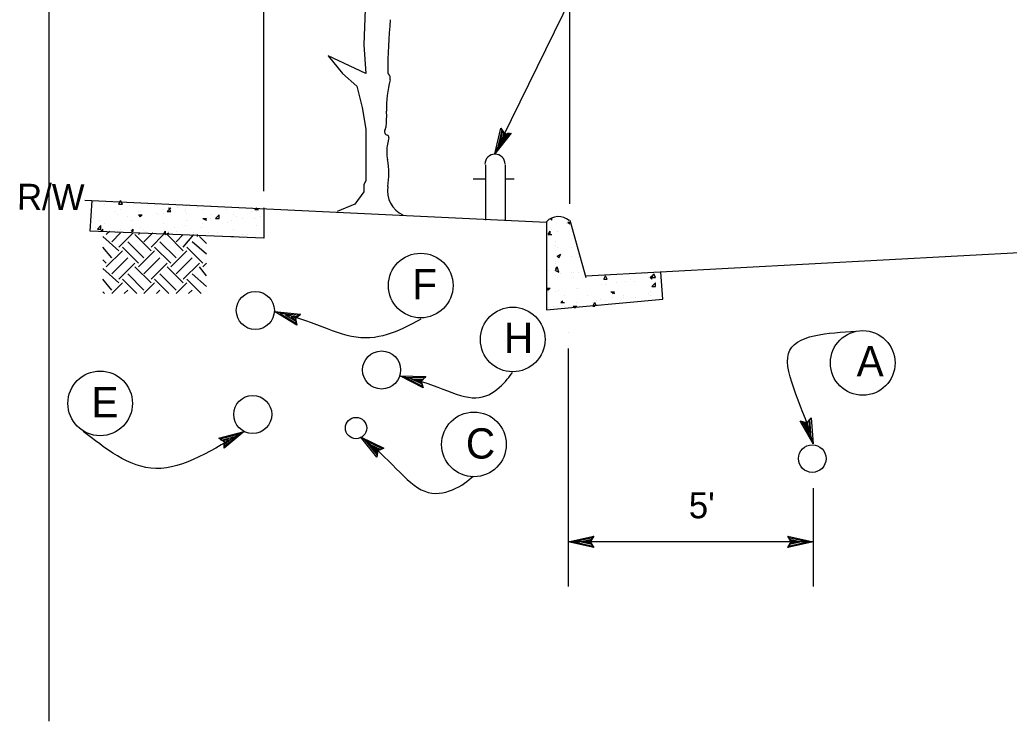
# Model space of a CAD drawing. Extents: x -119017 to -116080, y -104449 to -102845.
# Drawn here: x -118751.6 to -118523, y -103240.9 to -103078.8 of the extents above; entities that cross this region are included whole.
import ezdxf

# ---------------------------------------------------------------- set-up
doc = ezdxf.new("R2010")
doc.units = 0
for name, color, linetype in [('G-MARK', 7, 'Continuous'), ('G-TEXT', 7, 'Continuous'), ('Misc CnstDet(22)', 7, 'Continuous')]:
    doc.layers.add(name, color=color, linetype=linetype)

msp = doc.modelspace()

# ---------------------------------------------------------------- linework, layer by layer
at = {"layer": 'G-MARK'}
for p, q in [((-118695.17, -103118.46), (-118695.17, -103063.48)), ((-118624.48, -103121.36), (-118624.48, -103063.48)), ((-118624.9, -103154.84), (-118624.9, -103209.82)), ((-118568.26, -103187.09), (-118568.26, -103209.82)), ((-118568.26, -103199.49), (-118624.9, -103199.49))]:
    msp.add_line(p, q, dxfattribs=at)
msp.add_lwpolyline([(-118641.89, -103109.89), (-118614.2, -103053.25), (-118603.86, -103053.25)], dxfattribs=at)
for centre in [(-118658.96, -103140.25), (-118637.7, -103152.72), (-118556.82, -103158.14), (-118733.02, -103167.48), (-118646.66, -103176.97)]:
    msp.add_circle(centre, 7.47, dxfattribs=at)
for points in [[(-118692.74, -103146.26), (-118684.47, -103147.92), (-118672.48, -103155.77), (-118661.74, -103149.57), (-118658.84, -103147.92)], [(-118568.31, -103176.85), (-118569.96, -103169.41), (-118580.71, -103151.64), (-118564.59, -103151.23), (-118558.39, -103150.81)], [(-118663.8, -103161.15), (-118656.36, -103162.39), (-118644.79, -103170.24), (-118639, -103161.97), (-118637.76, -103160.32)], [(-118699.77, -103173.96), (-118706.79, -103178.1), (-118720.85, -103187.19), (-118732.01, -103177.68), (-118736.97, -103173.96)], [(-118672.9, -103175.2), (-118666.28, -103179.75), (-118658.43, -103192.56), (-118648.92, -103186.36), (-118646.85, -103184.3)]]:
    msp.add_open_spline(points, degree=3, dxfattribs=at)
at = {"layer": 'G-TEXT'}
for points in [[(-118638.06, -103105.07), (-118641.85, -103109.79), (-118640.42, -103103.91), (-118640.2, -103104.26), (-118641.25, -103108.56), (-118638.47, -103105.11), (-118638.87, -103105.14), (-118640.65, -103107.35), (-118639.98, -103104.6), (-118639.76, -103104.94), (-118640.05, -103106.13), (-118639.28, -103105.17), (-118639.59, -103105.2), (-118640.42, -103103.91), (-118639.59, -103105.2)], [(-118687.56, -103149.39), (-118692.74, -103146.26), (-118686.72, -103146.9), (-118687.03, -103147.16), (-118691.44, -103146.7), (-118687.64, -103148.99), (-118687.73, -103148.59), (-118690.16, -103147.13), (-118687.34, -103147.42), (-118687.65, -103147.69), (-118688.87, -103147.56), (-118687.82, -103148.2), (-118687.89, -103147.89), (-118686.72, -103146.9), (-118687.89, -103147.89)], [(-118658.4, -103163.86), (-118663.8, -103161.15), (-118657.76, -103161.31), (-118658.04, -103161.6), (-118662.47, -103161.48), (-118658.51, -103163.47), (-118658.63, -103163.08), (-118661.17, -103161.81), (-118658.33, -103161.89), (-118658.62, -103162.18), (-118659.85, -103162.14), (-118658.75, -103162.7), (-118658.84, -103162.39), (-118657.76, -103161.31), (-118658.84, -103162.39)], [(-118568.76, -103170.82), (-118568.31, -103176.85), (-118571.28, -103171.58), (-118570.88, -103171.68), (-118568.71, -103175.55), (-118569.03, -103171.12), (-118569.31, -103171.42), (-118569.1, -103174.25), (-118570.49, -103171.78), (-118570.09, -103171.88), (-118569.49, -103172.95), (-118569.58, -103171.72), (-118569.79, -103171.96), (-118571.28, -103171.58), (-118569.79, -103171.96)], [(-118705.61, -103175.53), (-118699.77, -103173.96), (-118704.39, -103177.86), (-118704.37, -103177.46), (-118700.98, -103174.6), (-118705.26, -103175.75), (-118704.92, -103175.96), (-118702.18, -103175.22), (-118704.34, -103177.05), (-118704.32, -103176.64), (-118703.38, -103175.85), (-118704.57, -103176.17), (-118704.3, -103176.34), (-118704.39, -103177.86), (-118704.3, -103176.34)], [(-118669.06, -103179.88), (-118672.9, -103175.2), (-118667.44, -103177.82), (-118667.82, -103177.96), (-118671.82, -103176.04), (-118669.01, -103179.48), (-118668.96, -103179.08), (-118670.76, -103176.88), (-118668.2, -103178.11), (-118668.58, -103178.25), (-118669.69, -103177.72), (-118668.91, -103178.67), (-118668.87, -103178.36), (-118667.44, -103177.82), (-118668.87, -103178.36)], [(-118618.99, -103200.81), (-118624.9, -103199.49), (-118618.99, -103198.18), (-118619.2, -103198.53), (-118623.53, -103199.48), (-118619.2, -103200.46), (-118619.41, -103200.11), (-118622.18, -103199.49), (-118619.41, -103198.88), (-118619.62, -103199.23), (-118620.82, -103199.49), (-118619.62, -103199.76), (-118619.78, -103199.49), (-118618.99, -103198.18), (-118619.78, -103199.49)], [(-118574.17, -103198.17), (-118568.26, -103199.49), (-118574.17, -103200.8), (-118573.96, -103200.45), (-118569.63, -103199.49), (-118573.96, -103198.52), (-118573.75, -103198.87), (-118570.98, -103199.49), (-118573.75, -103200.1), (-118573.54, -103199.75), (-118572.34, -103199.49), (-118573.54, -103199.22), (-118573.38, -103199.49), (-118574.17, -103200.8), (-118573.38, -103199.49)]]:
    msp.add_lwpolyline(points, close=True, dxfattribs=at)
at = {"layer": 'Misc CnstDet(22)'}
for p, q in [((-118744.83, -103240.93), (-118744.83, -102917.66)), ((-118624.48, -103121.36), (-118624.48, -103063.48)), ((-118643.96, -103112.37), (-118643.96, -103125.18)), ((-118639.41, -103112.37), (-118639.41, -103125.18)), ((-118643.96, -103115.67), (-118646.85, -103115.67)), ((-118637.35, -103115.67), (-118639.41, -103115.67)), ((-118736.6, -103120.5), (-118629.9, -103125.6)), ((-118735.32, -103127.66), (-118734.9, -103120.63)), ((-118734.49, -103121.05), (-118734.49, -103121.05)), ((-118734.49, -103121.46), (-118734.49, -103121.46)), ((-118732.01, -103121.46), (-118732.01, -103121.46)), ((-118730.36, -103121.05), (-118730.36, -103121.05)), ((-118728.7, -103121.46), (-118728.29, -103120.63)), ((-118728.7, -103121.46), (-118727.88, -103121.46)), ((-118727.88, -103121.46), (-118728.29, -103120.63)), ((-118726.22, -103121.87), (-118726.22, -103121.87)), ((-118722.09, -103121.87), (-118722.09, -103121.87)), ((-118720.44, -103121.87), (-118720.44, -103121.87)), ((-118713, -103121.87), (-118713, -103121.87)), ((-118707.21, -103121.87), (-118707.21, -103121.87)), ((-118734.49, -103123.94), (-118734.49, -103123.94)), ((-118729.53, -103123.11), (-118729.53, -103123.11)), ((-118729.12, -103123.94), (-118729.12, -103123.94)), ((-118728.29, -103122.7), (-118728.29, -103122.7)), ((-118724.16, -103123.11), (-118724.16, -103123.11)), ((-118724.16, -103123.94), (-118723.74, -103124.36)), ((-118724.16, -103123.94), (-118723.33, -103123.94)), ((-118723.74, -103123.11), (-118723.74, -103123.11)), ((-118723.74, -103123.94), (-118723.74, -103123.94)), ((-118723.74, -103124.36), (-118723.33, -103123.94)), ((-118720.02, -103123.53), (-118720.02, -103123.53)), ((-118719.61, -103123.94), (-118719.61, -103123.94)), ((-118718.37, -103122.7), (-118718.37, -103122.7)), ((-118718.37, -103123.53), (-118718.37, -103123.53)), ((-118717.54, -103123.11), (-118716.72, -103122.29)), ((-118717.54, -103123.11), (-118716.72, -103123.11)), ((-118716.72, -103123.11), (-118717.13, -103122.29)), ((-118715.06, -103122.29), (-118715.06, -103122.29)), ((-118713.41, -103122.7), (-118713.41, -103122.7)), ((-118713.41, -103123.11), (-118713.41, -103123.11)), ((-118713, -103123.53), (-118713, -103123.53)), ((-118710.52, -103122.29), (-118710.52, -103122.29)), ((-118709.27, -103122.7), (-118709.27, -103122.7)), ((-118707.21, -103123.94), (-118707.21, -103123.94)), ((-118706.38, -103124.77), (-118705.55, -103123.94)), ((-118705.55, -103124.77), (-118705.55, -103123.94)), ((-118703.9, -103122.7), (-118703.9, -103122.7)), ((-118702.25, -103123.94), (-118702.25, -103123.94)), ((-118698.11, -103123.11), (-118698.11, -103123.11)), ((-118697.29, -103122.7), (-118696.87, -103122.29)), ((-118697.29, -103122.7), (-118696.46, -103122.7)), ((-118696.87, -103122.7), (-118696.87, -103122.29)), ((-118696.87, -103123.11), (-118696.87, -103123.11)), ((-118695.22, -103122.29), (-118695.22, -103129.32)), ((-118695.17, -103122.19), (-118695.17, -103122.19)), ((-118734.49, -103124.77), (-118734.49, -103124.77)), ((-118733.66, -103127.25), (-118732.84, -103126.42)), ((-118733.25, -103125.18), (-118733.25, -103125.18)), ((-118732.84, -103127.25), (-118732.84, -103126.42)), ((-118732.01, -103126.01), (-118732.01, -103126.01)), ((-118726.64, -103124.36), (-118726.64, -103124.36)), ((-118725.81, -103125.18), (-118725.81, -103125.18)), ((-118718.37, -103126.01), (-118718.37, -103126.01)), ((-118713.41, -103126.42), (-118713.41, -103126.42)), ((-118713, -103125.18), (-118713, -103125.18)), ((-118709.27, -103124.77), (-118708.45, -103125.18)), ((-118709.27, -103124.77), (-118708.45, -103124.77)), ((-118709.27, -103126.01), (-118709.27, -103126.01)), ((-118708.86, -103125.18), (-118708.45, -103124.77)), ((-118707.62, -103124.77), (-118707.62, -103124.77)), ((-118706.38, -103124.77), (-118705.55, -103124.77)), ((-118703.49, -103125.6), (-118703.49, -103125.6)), ((-118702.66, -103125.18), (-118702.66, -103125.18)), ((-118701.42, -103124.36), (-118701.42, -103124.36)), ((-118700.18, -103124.77), (-118700.18, -103124.77)), ((-118697.29, -103124.77), (-118697.29, -103124.77)), ((-118696.87, -103126.42), (-118696.87, -103126.42)), ((-118696.05, -103124.36), (-118696.05, -103124.36)), ((-118696.05, -103124.36), (-118696.05, -103124.36)), ((-118629.9, -103125.6), (-118629.9, -103145.85)), ((-118629.9, -103126.42), (-118629.9, -103126.42)), ((-118629.08, -103124.77), (-118628.66, -103125.18)), ((-118628.66, -103125.18), (-118628.66, -103124.77)), ((-118625.36, -103126.01), (-118625.36, -103126.01)), ((-118624.94, -103125.6), (-118624.53, -103126.01)), ((-118624.94, -103125.6), (-118624.53, -103125.6)), ((-118624.94, -103126.01), (-118624.94, -103126.01)), ((-118624.53, -103125.18), (-118620.81, -103138.41)), ((-118624.53, -103126.01), (-118624.53, -103126.01)), ((-118624.48, -103125.08), (-118624.48, -103125.08)), ((-118624.48, -103125.08), (-118624.48, -103125.08)), ((-118695.22, -103129.32), (-118735.32, -103127.66)), ((-118734.08, -103126.84), (-118734.08, -103126.84)), ((-118733.66, -103127.25), (-118732.84, -103127.25)), ((-118732.84, -103127.66), (-118732.42, -103127.25)), ((-118732.84, -103127.66), (-118732.42, -103127.66)), ((-118732.42, -103127.66), (-118732.42, -103127.25)), ((-118731.6, -103128.49), (-118730.77, -103127.66)), ((-118730.36, -103130.14), (-118728.29, -103128.08)), ((-118729.12, -103127.66), (-118729.12, -103127.66)), ((-118728.7, -103131.38), (-118725.4, -103128.08)), ((-118728.29, -103127.25), (-118728.29, -103127.25)), ((-118725.81, -103127.66), (-118725.4, -103127.25)), ((-118725.81, -103127.66), (-118725.4, -103127.66)), ((-118725.4, -103127.66), (-118725.4, -103127.25)), ((-118721.26, -103132.21), (-118724.98, -103128.49)), ((-118724.16, -103128.49), (-118723.74, -103128.08)), ((-118723.74, -103126.84), (-118723.74, -103126.84)), ((-118722.92, -103127.25), (-118722.92, -103127.25)), ((-118722.92, -103130.14), (-118720.85, -103128.08)), ((-118722.5, -103127.66), (-118722.5, -103127.66)), ((-118721.26, -103131.38), (-118718.37, -103128.49)), ((-118718.37, -103128.49), (-118717.96, -103127.66)), ((-118717.96, -103128.49), (-118717.96, -103127.66)), ((-118717.96, -103128.49), (-118717.13, -103128.08)), ((-118717.96, -103128.49), (-118717.96, -103128.49)), ((-118717.54, -103128.49), (-118717.13, -103128.08)), ((-118713.82, -103132.21), (-118717.54, -103128.49)), ((-118717.13, -103127.66), (-118717.13, -103127.66)), ((-118716.72, -103128.49), (-118716.72, -103128.49)), ((-118715.89, -103126.84), (-118715.89, -103126.84)), ((-118715.48, -103127.66), (-118715.48, -103127.66)), ((-118715.48, -103130.14), (-118713.82, -103128.49)), ((-118713.82, -103131.38), (-118711.34, -103128.49)), ((-118711.34, -103128.08), (-118711.34, -103128.08)), ((-118710.52, -103128.9), (-118710.52, -103128.49)), ((-118710.52, -103128.9), (-118710.52, -103128.49)), ((-118709.69, -103126.84), (-118709.69, -103126.84)), ((-118708.03, -103128.08), (-118708.03, -103128.08)), ((-118705.97, -103128.08), (-118705.97, -103128.08)), ((-118702.25, -103127.25), (-118702.25, -103127.25)), ((-118700.18, -103128.49), (-118700.18, -103128.49)), ((-118698.94, -103128.49), (-118698.94, -103128.49)), ((-118629.49, -103128.49), (-118629.08, -103127.66)), ((-118629.49, -103128.49), (-118628.66, -103128.49)), ((-118629.08, -103126.84), (-118629.08, -103126.84)), ((-118629.08, -103128.49), (-118629.08, -103127.66)), ((-118628.66, -103127.25), (-118628.66, -103127.25)), ((-118627.42, -103127.66), (-118627.42, -103127.66)), ((-118620.81, -103138), (-118436.44, -103128.08)), ((-118728.7, -103132.21), (-118732.42, -103128.9)), ((-118722.92, -103133.86), (-118726.64, -103130.14)), ((-118715.48, -103133.86), (-118719.2, -103130.14)), ((-118708.45, -103133.04), (-118711.76, -103130.14)), ((-118708.45, -103130.56), (-118710.1, -103128.9)), ((-118703.07, -103128.9), (-118703.07, -103128.9)), ((-118702.66, -103128.9), (-118702.25, -103128.9)), ((-118702.25, -103128.9), (-118702.25, -103128.9)), ((-118627.84, -103130.14), (-118627.84, -103130.14)), ((-118627.84, -103130.97), (-118627.84, -103130.97)), ((-118730.36, -103133.86), (-118732.42, -103131.38)), ((-118731.6, -103135.93), (-118727.88, -103132.21)), ((-118724.16, -103135.1), (-118727.88, -103131.38)), ((-118724.16, -103135.93), (-118720.44, -103132.21)), ((-118716.72, -103135.1), (-118720.44, -103131.38)), ((-118716.72, -103135.93), (-118713, -103132.21)), ((-118709.27, -103135.1), (-118713, -103131.38)), ((-118627.42, -103131.38), (-118627.42, -103131.38)), ((-118627.42, -103133.45), (-118626.6, -103133.04)), ((-118627.42, -103133.45), (-118627.01, -103133.86)), ((-118627.01, -103133.86), (-118626.6, -103133.04)), ((-118624.12, -103131.38), (-118624.12, -103131.38)), ((-118624.12, -103133.45), (-118624.12, -103133.45)), ((-118731.6, -103135.1), (-118732.42, -103134.28)), ((-118730.36, -103137.58), (-118726.64, -103133.86)), ((-118728.7, -103138.82), (-118724.98, -103135.1)), ((-118722.92, -103137.58), (-118719.2, -103133.86)), ((-118721.26, -103138.82), (-118717.54, -103135.1)), ((-118715.48, -103137.58), (-118711.76, -103133.86)), ((-118713.82, -103138.82), (-118710.1, -103135.1)), ((-118709.27, -103135.93), (-118708.45, -103135.1)), ((-118627.84, -103134.69), (-118627.84, -103134.69)), ((-118627.84, -103135.1), (-118627.84, -103135.1)), ((-118622.46, -103133.86), (-118622.46, -103133.86)), ((-118728.7, -103139.65), (-118732.42, -103136.34)), ((-118722.92, -103141.3), (-118726.64, -103137.58)), ((-118721.26, -103139.65), (-118724.98, -103135.93)), ((-118715.48, -103141.3), (-118719.2, -103137.58)), ((-118713.82, -103139.65), (-118717.54, -103135.93)), ((-118708.45, -103140.48), (-118711.76, -103137.58)), ((-118708.45, -103138), (-118710.1, -103135.93)), ((-118629.49, -103136.76), (-118629.49, -103136.76)), ((-118627.84, -103136.76), (-118627.42, -103135.93)), ((-118627.84, -103136.34), (-118627.42, -103135.93)), ((-118627.84, -103136.34), (-118627.42, -103136.34)), ((-118627.84, -103136.76), (-118627.01, -103137.17)), ((-118627.84, -103138), (-118627.84, -103138)), ((-118627.01, -103137.17), (-118627.42, -103135.93)), ((-118627.42, -103136.34), (-118627.42, -103135.93)), ((-118626.6, -103137.58), (-118626.6, -103137.58)), ((-118624.12, -103137.17), (-118624.12, -103137.17)), ((-118623.7, -103137.17), (-118623.7, -103137.17)), ((-118622.46, -103137.17), (-118622.46, -103137.17)), ((-118616.68, -103138.82), (-118616.26, -103138)), ((-118615.85, -103138.82), (-118616.26, -103138)), ((-118612.54, -103137.58), (-118612.54, -103137.58)), ((-118612.54, -103137.58), (-118612.54, -103137.58)), ((-118607.17, -103137.58), (-118607.17, -103137.58)), ((-118605.93, -103138.41), (-118605.52, -103138)), ((-118605.52, -103138.41), (-118605.1, -103137.58)), ((-118605.52, -103138.82), (-118605.52, -103138)), ((-118604.69, -103138.41), (-118605.1, -103137.58)), ((-118603.03, -103143.37), (-118603.45, -103137.17)), ((-118730.36, -103141.3), (-118732.42, -103138.82)), ((-118730.36, -103142.13), (-118727.88, -103139.65)), ((-118724.57, -103142.13), (-118727.88, -103138.82)), ((-118722.92, -103142.13), (-118720.44, -103139.65)), ((-118717.13, -103142.13), (-118720.44, -103138.82)), ((-118715.48, -103142.13), (-118713, -103139.65)), ((-118709.69, -103142.13), (-118713, -103138.82)), ((-118627.42, -103138.41), (-118627.42, -103138.41)), ((-118623.7, -103138.41), (-118623.7, -103138.41)), ((-118621.64, -103138.41), (-118621.64, -103138.41)), ((-118617.09, -103140.06), (-118617.09, -103140.06)), ((-118616.68, -103138.82), (-118615.85, -103138.82)), ((-118616.26, -103138.82), (-118616.26, -103138.82)), ((-118616.26, -103140.06), (-118616.26, -103140.06)), ((-118613.78, -103139.65), (-118613.78, -103139.65)), ((-118611.72, -103139.24), (-118611.72, -103139.24)), ((-118610.48, -103138.82), (-118610.48, -103138.82)), ((-118609.65, -103139.24), (-118609.65, -103139.24)), ((-118606.34, -103138.41), (-118606.34, -103138.41)), ((-118605.93, -103138.41), (-118605.52, -103138.82)), ((-118605.52, -103138.41), (-118604.69, -103138.41)), ((-118605.52, -103140.48), (-118604.69, -103139.65)), ((-118604.69, -103139.24), (-118604.69, -103139.24)), ((-118604.69, -103140.48), (-118604.69, -103139.65)), ((-118732.01, -103142.13), (-118732.42, -103141.72)), ((-118727.46, -103142.13), (-118726.64, -103141.3)), ((-118720.02, -103142.13), (-118719.2, -103141.3)), ((-118712.58, -103142.13), (-118711.76, -103141.3)), ((-118629.9, -103140.89), (-118629.49, -103141.3)), ((-118629.9, -103140.89), (-118629.08, -103140.89)), ((-118629.49, -103141.3), (-118629.08, -103140.89)), ((-118629.49, -103141.72), (-118629.49, -103141.72)), ((-118627.84, -103141.72), (-118627.84, -103141.72)), ((-118627.01, -103141.3), (-118627.01, -103141.3)), ((-118625.77, -103142.54), (-118625.77, -103142.54)), ((-118622.88, -103140.89), (-118622.88, -103140.89)), ((-118622.46, -103140.89), (-118622.46, -103140.89)), ((-118620.4, -103142.54), (-118620.4, -103142.54)), ((-118615.02, -103141.72), (-118614.2, -103142.13)), ((-118615.02, -103141.72), (-118614.2, -103141.72)), ((-118614.61, -103142.13), (-118614.2, -103141.72)), ((-118612.13, -103142.54), (-118612.13, -103142.54)), ((-118606.34, -103142.13), (-118606.34, -103142.13)), ((-118605.93, -103141.72), (-118605.93, -103141.72)), ((-118605.93, -103142.54), (-118605.93, -103142.54)), ((-118605.52, -103140.48), (-118604.69, -103140.48)), ((-118629.9, -103145.85), (-118603.03, -103143.37)), ((-118626.6, -103144.2), (-118626.18, -103143.78)), ((-118626.6, -103144.2), (-118625.77, -103144.2)), ((-118626.18, -103144.2), (-118626.18, -103143.78)), ((-118622.88, -103144.2), (-118622.88, -103144.2)), ((-118619.16, -103144.2), (-118619.16, -103144.2)), ((-118619.16, -103145.02), (-118618.74, -103144.2)), ((-118618.33, -103145.02), (-118618.74, -103144.2)), ((-118618.33, -103143.78), (-118618.33, -103143.78)), ((-118617.5, -103143.37), (-118617.5, -103143.37)), ((-118616.26, -103143.78), (-118616.26, -103143.78)), ((-118614.61, -103142.96), (-118614.61, -103142.96)), ((-118612.54, -103143.37), (-118612.54, -103143.37)), ((-118612.13, -103142.96), (-118612.13, -103142.96)), ((-118609.24, -103142.96), (-118609.24, -103142.96)), ((-118603.45, -103143.37), (-118603.45, -103143.37)), ((-118629.49, -103145.44), (-118629.49, -103145.44)), ((-118628.25, -103145.02), (-118628.25, -103145.02)), ((-118625.77, -103145.02), (-118625.77, -103145.02)), ((-118624.12, -103145.02), (-118624.12, -103145.02)), ((-118623.7, -103145.02), (-118623.29, -103145.44)), ((-118623.7, -103145.02), (-118622.88, -103145.02)), ((-118623.29, -103145.44), (-118622.88, -103145.02)), ((-118619.16, -103145.02), (-118618.74, -103145.02)), ((-118624.9, -103151.12), (-118624.9, -103151.12)), ((-118568.26, -103183.37), (-118568.26, -103183.37)), ((-118624.9, -103199.49), (-118624.9, -103199.49))]:
    msp.add_line(p, q, dxfattribs=at)
msp.add_lwpolyline([(-118684.06, -103049.95), (-118673.31, -103056.15), (-118671.24, -103061.93), (-118672.07, -103084.67), (-118671.66, -103091.28), (-118680.34, -103087.15), (-118677.03, -103091.28), (-118673.72, -103094.18), (-118672.48, -103099.14), (-118671.66, -103104.1), (-118671.66, -103110.71), (-118671.66, -103116.09), (-118672.07, -103116.91), (-118672.07, -103118.57), (-118674.14, -103121.46), (-118678.27, -103123.11)], dxfattribs=at)
for centre, radius in [((-118697.17, -103146.02), 4.4), ((-118667.99, -103159.77), 4.4), ((-118697.77, -103170.05), 4.4), ((-118673.89, -103173.19), 2.47), ((-118568.49, -103180.24), 3.19)]:
    msp.add_circle(centre, radius, dxfattribs=at)
for centre, radius, start, end in [((-118528.52, -103091.38), 138.04, 174.7885, 179.8308), ((-118666.04, -103090.98), 0.517, 179.8308, 226.0196), ((-118667.37, -103092.35), 1.39, 345.1915, 46.0196), ((-118641.75, -103099.13), 25.1, 165.1915, 181.9609), ((-118694.67, -103100.94), 27.85, 355.062, 1.9609), ((-118669.14, -103103.14), 2.23, 331.6229, 355.062), ((-118666.37, -103104.64), 0.928, 151.6229, 252.4177), ((-118666.79, -103105.98), 0.471, 344.3625, 72.4177), ((-118656.44, -103109.25), 10.36, 170.5692, 190.7045), ((-118653.14, -103109.8), 13.7, 164.3625, 170.5692), ((-118641.79, -103112.22), 2.33, 0, 180), ((-118683.61, -103114.38), 17.3, 350.0213, 10.7045), ((-118660.6, -103118.37), 6.06, 170.6027, 246.0808), ((-118627.14, -103128.21), 3.88, 49.4724, 135.9655)]:
    msp.add_arc(centre, radius, start, end, dxfattribs=at)

# ---------------------------------------------------------------- texts
msp.add_text('R/W', height=6, rotation=359.6007, dxfattribs=at).set_placement((-118752.25, -103122.73))
for s, height, p in [('F', 7, (-118660.9, -103143.44)), ('H', 7, (-118639.74, -103155.85)), ('A', 7, (-118558.23, -103161.22)), ('E', 7, (-118735.03, -103170.73)), ('C', 7, (-118648.52, -103180.24)), ("5'", 6, (-118597.01, -103194.04))]:
    msp.add_text(s, height=height, dxfattribs=at).set_placement(p)

doc.saveas('drawing.dxf')
